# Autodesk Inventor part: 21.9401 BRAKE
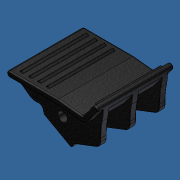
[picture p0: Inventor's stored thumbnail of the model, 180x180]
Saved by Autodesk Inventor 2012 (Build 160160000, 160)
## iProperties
Created: 2010-10
Part Number: 21.9401 BRAKE
Document SubType Name: Modeling
Designer: Administrator
Density: 1.4 g/cm^3
Material: PVC-U
Mass: 27.9567 g
Surface Area: 97.5019 cm^2
Volume: 19.969 cm^3
Author: Administrator
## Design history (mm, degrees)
feature "Base1"
body "Solid1"
